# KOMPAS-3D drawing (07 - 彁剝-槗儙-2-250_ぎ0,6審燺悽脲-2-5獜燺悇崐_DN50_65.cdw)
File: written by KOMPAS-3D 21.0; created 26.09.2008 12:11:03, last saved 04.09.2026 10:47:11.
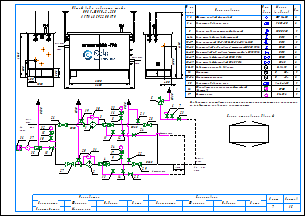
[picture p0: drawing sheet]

Sheets 1-2: A3, landscape

Document properties: Наименование: Макро:21; Автор: RaskoAdmin; Форматы листов документа: 2xA3; Полное имя файла: \\UR38nt01\Departments\КТО\КБ ПУРДГ\Заявки\Прайс-лист на типовые шкафы ГРПШ\ПРДГ_стандарт_20_03_2026\ПРДГ с РДНК\ПРДГ-ШУГО-2-250_до0,6МПа_Рвых-2-5кПа_РДНК_DN50_65.cdw

Title block, sheet 1: Наименование: Пункт учета газа / ПУГ-Ш-400-Р / ЛГТИ.485922.001ТУ; designation: ЛГТИ.03.4411141; sheet number: 1; Количество листов документа: 2; organisation: ООО "ЭЛЬСТЕР Газэлектроника"; Форматы листов документа: A3; stored path: C:\Рабочие документы\Компас\ПУГ\Схема.cdw; Разработал: Устинов; Проверил: Кошкин; Утвердил: Кошкин
Title block, sheet 2: sheet number: 2; stored path: D:\Рабочие документы\Заявки\ПУРДГ\ПУРДГ-ШУЭО-2-100-Р 4411220.cdw; designation, second copy: ЛГТИ.03.4411141-

Views: Вид 1, Вид 2
Referenced files: wcvoit.frw
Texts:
  Normal
  Вход
  газа
  PDI
  Выход
  Р=     кПа
  DN65
  DN50
  DN20
  Импульс DN15
  ≥5DN
  HYSWLongFangSong
  № на
  схеме
  Усл.
  обозн.
  Марка
  (модель)
  Кол.
  Фильтр газовый фланцевый
  ФГ 16-50
  Регулятор давления газа
  РДНК-50
  Клапан предохранительный сбросной
  КПС DN20
  Кран шаровой газовый латунный
  DN15
  Кран кнопочный VE-РАСКО-НЗ-1,6-G1/2-М20
  Кран шаровой "под приварку" штуцерный DN20 PN16
  Кран шаровой "под приварку" штуцерный п/п DN15 PN16
  Кран шаровой фланцевый DN50 PN16
  Кран шаровой фланцевый DN65 PN16
  Индикатор перепада давления
  Delta 15
  Манометр
  Манометр-напоромер
  0...     МПа
  0...     кПа
  Обогреватель газогорелочный шкафной
  (Эльтон")
  Счетчик газа
  Venio-A-15
  ОГШН
  BK-G1,6
  Общий вид и габариты шкафа
  ПРДГ-ШУГО-2-250
  Выход газа
  Вход газа
  Схема открывания дверей
  logo-rasko-ge.png
  Предприятие изготовитель может заменять комплектующие на аналогичные,
  не ухудшающие заявленных характеристик.
  Р=        МПа
  Должность
  Конструктор
  Фамилия
  Подпись
  Дата
  Согласовано
  Максимкин
  Лист
  Листов
  POLYLINE_STYLE_0.18_RGB_0_0_0
  POLYLINE_STYLE_0.50_RGB_0_0_0
  POLYLINE_STYLE_0.34_RGB_0_0_0
  PHANTOM_RGB_0_0_0_SC_1_THICK_0.18
  K5LT_THIN_RGB_0_0_0_THICK_0.18
  K5LT32769_RGB_0_0_0_THICK_0.18
  K5LT12_RGB_0_0_0_SC_1_THICK_0.18
  K5LT_DASHED_RGB_0_0_0_SC_1_THICK_0.18
  ACISOTGL_RGB_0_0_0_SC_0.8_THICK_0.25
  CONTINUOUS_RGB_0_127_31_THICK_0.3
  CONTINUOUS_RGB_0_0_255_THICK_0.35
  CONTINUOUS_RGB_255_0_0_THICK_0.35
  POLYLINE_STYLE_0.25_RGB_0_0_0
  CONTINUOUS_RGB_0_0_0_THICK_0.5
  POLYLINE_STYLE_0.35_RGB_0_0_255
  CONTINUOUS_RGB_0_0_0_THICK_0.4
  CONTINUOUS_RGB_0_0_0_THICK_0.35
  Без оформления
Dimensions and other numbers on the sheet: 1; 2; 3; 4; 5; 10; 27; 28; 29; 23; 8; 12; 18; 19; 20; 21; 22; 25; 24; 30; 31; 15; 16; 35; 36; 26; 6; 7; 11; 14; 13; 33; 1, 2; 3, 4; 6-14; 9; 15-17; 18-23; 24-25; 26-27; 28-29; 30-31; 32; 33-34; 37; 400; 1050; 500; 305; 2300; 1565; 2600; 17; 34; 1000; 4130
